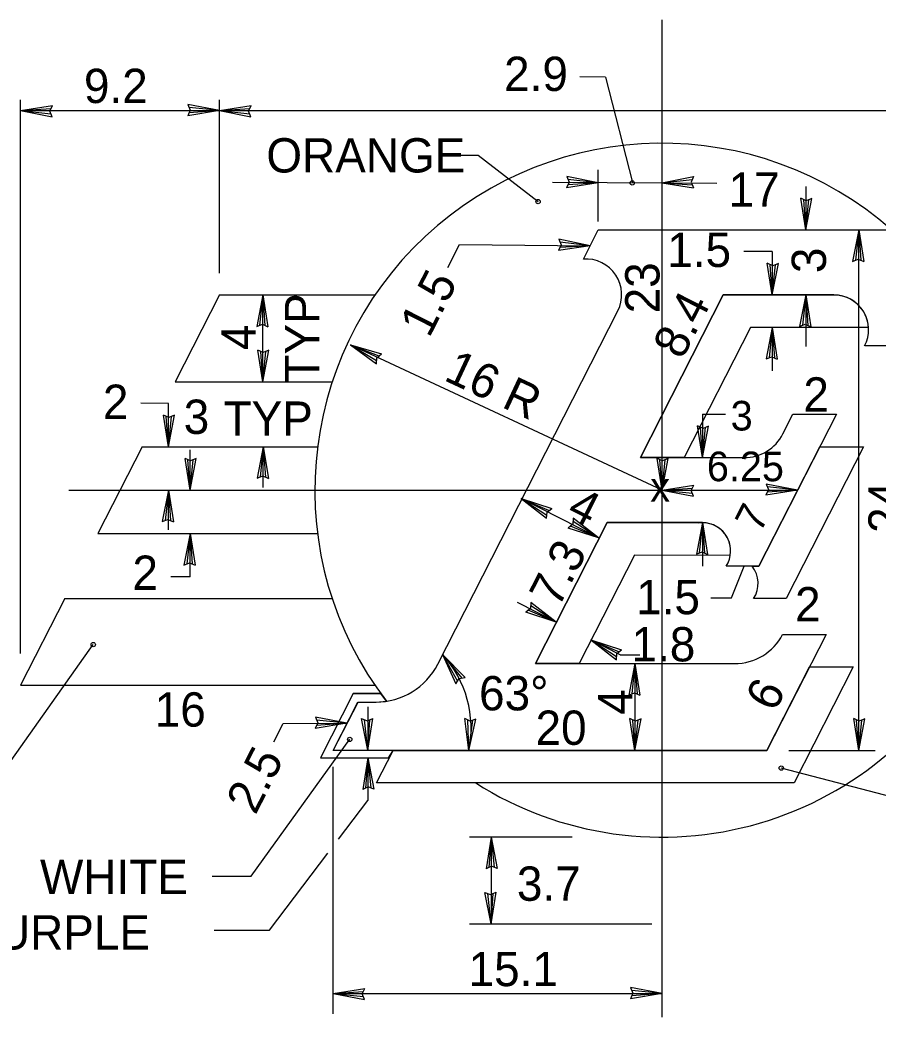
# Model space of a CAD drawing. Extents: x 10268197 to 10269179, y 2141503 to 2142677.
# Drawn here: x 10268467.86 to 10268485.36, y 2142117.75 to 2142138.09 of the extents above; entities that cross this region are included whole.
import ezdxf

# ---------------------------------------------------------------- set-up
doc = ezdxf.new("R2010")
doc.units = 0
for name, color, linetype in [('1', 7, 'Continuous'), ('2', 7, 'Continuous'), ('52', 7, 'Continuous'), ('SOILS_SP83_SHP', 7, 'Continuous')]:
    doc.layers.add(name, color=color, linetype=linetype)

msp = doc.modelspace()

# ---------------------------------------------------------------- linework, layer by layer
at = {"layer": '1'}
for p, q in [((10268480.958, 2142117.747), (10268480.958, 2142138.09)), ((10268479.802, 2142136.926), (10268479.281, 2142136.929)), ((10268479.802, 2142136.926), (10268480.353, 2142134.772)), ((10268467.878, 2142125.164), (10268467.878, 2142136.461)), ((10268471.932, 2142132.921), (10268471.932, 2142136.461)), ((10268467.878, 2142136.24), (10268491.08, 2142136.24)), ((10268476.41, 2142135.328), (10268477.21, 2142135.328)), ((10268477.21, 2142135.328), (10268478.431, 2142134.386)), ((10268479.658, 2142133.976), (10268479.658, 2142135.032)), ((10268482.078, 2142134.75), (10268478.725, 2142134.774)), ((10268483.89, 2142134.691), (10268483.89, 2142133.806)), ((10268484.969, 2142123.188), (10268484.969, 2142133.806)), ((10268476.59, 2142133.039), (10268476.829, 2142133.508)), ((10268476.829, 2142133.508), (10268479.495, 2142133.484)), ((10268483.206, 2142133.364), (10268482.628, 2142133.364)), ((10268483.206, 2142133.364), (10268483.206, 2142132.479)), ((10268472.817, 2142130.709), (10268472.817, 2142132.479)), ((10268480.517, 2142129.161), (10268482.207, 2142132.479)), ((10268482.207, 2142132.479), (10268484.462, 2142132.479)), ((10268483.89, 2142132.479), (10268483.89, 2142131.427)), ((10268482.763, 2142131.815), (10268481.411, 2142129.161)), ((10268485.17, 2142131.815), (10268482.763, 2142131.815)), ((10268483.206, 2142131.815), (10268483.206, 2142130.93)), ((10268480.958, 2142128.497), (10268474.605, 2142131.459)), ((10268470.892, 2142130.267), (10268470.332, 2142130.27)), ((10268470.892, 2142129.382), (10268470.892, 2142130.267)), ((10268481.783, 2142130.046), (10268481.783, 2142129.161)), ((10268481.783, 2142130.046), (10268482.252, 2142130.046)), ((10268471.334, 2142128.497), (10268471.334, 2142129.322)), ((10268472.827, 2142128.552), (10268472.827, 2142129.382)), ((10268482.934, 2142126.949), (10268484.174, 2142129.382)), ((10268485.067, 2142129.382), (10268483.489, 2142126.285)), ((10268484.174, 2142129.382), (10268485.067, 2142129.382)), ((10268481.411, 2142129.161), (10268480.517, 2142129.161)), ((10268468.86, 2142128.497), (10268483.723, 2142128.497)), ((10268470.892, 2142127.689), (10268470.892, 2142128.497)), ((10268479.664, 2142127.521), (10268478.087, 2142128.325)), ((10268478.376, 2142124.957), (10268479.841, 2142127.834)), ((10268479.841, 2142127.834), (10268481.699, 2142127.827)), ((10268481.783, 2142127.834), (10268481.783, 2142126.949)), ((10268471.334, 2142126.727), (10268471.334, 2142127.612)), ((10268480.396, 2142127.168), (10268479.269, 2142124.957)), ((10268482.349, 2142127.162), (10268480.396, 2142127.168)), ((10268482.375, 2142126.297), (10268482.631, 2142126.949)), ((10268482.795, 2142126.949), (10268482.934, 2142126.949)), ((10268471.334, 2142126.727), (10268470.943, 2142126.731)), ((10268481.95, 2142126.297), (10268482.375, 2142126.297)), ((10268483.489, 2142126.285), (10268482.826, 2142126.285)), ((10268478.8, 2142125.802), (10268478.012, 2142126.204)), ((10268480.101, 2142125.139), (10268479.509, 2142125.44)), ((10268467.601, 2142122.868), (10268469.358, 2142125.347)), ((10268480.101, 2142125.139), (10268480.508, 2142125.139)), ((10268479.269, 2142124.957), (10268478.376, 2142124.957)), ((10268480.406, 2142124.957), (10268480.406, 2142123.188)), ((10268483.097, 2142123.188), (10268483.964, 2142124.89)), ((10268484.858, 2142124.89), (10268483.653, 2142122.524)), ((10268483.964, 2142124.89), (10268484.858, 2142124.89)), ((10268474.957, 2142124.074), (10268474.957, 2142123.195)), ((10268473.044, 2142123.365), (10268473.233, 2142123.734)), ((10268473.233, 2142123.734), (10268474.533, 2142123.745)), ((10268472.582, 2142120.624), (10268474.589, 2142123.413)), ((10268475.134, 2142122.524), (10268475.472, 2142123.188)), ((10268475.472, 2142123.188), (10268483.097, 2142123.188)), ((10268483.54, 2142123.188), (10268485.301, 2142123.188)), ((10268474.957, 2142123.038), (10268474.957, 2142122.165)), ((10268474.249, 2142117.811), (10268474.249, 2142122.849)), ((10268485.66, 2142122.233), (10268483.388, 2142122.827)), ((10268483.653, 2142122.524), (10268475.134, 2142122.524)), ((10268474.357, 2142121.373), (10268474.957, 2142122.165)), ((10268479.125, 2142121.418), (10268477.03, 2142121.418)), ((10268477.472, 2142121.418), (10268477.472, 2142119.648)), ((10268472.952, 2142119.519), (10268474.144, 2142121.093)), ((10268471.781, 2142120.624), (10268472.582, 2142120.624)), ((10268471.828, 2142119.519), (10268472.952, 2142119.519)), ((10268477.03, 2142119.648), (10268480.75, 2142119.648)), ((10268474.249, 2142118.227), (10268480.958, 2142118.227))]:
    msp.add_line(p, q, dxfattribs=at)
msp.add_lwpolyline([(10268475.223, 2142124.346), (10268474.658, 2142124.346), (10268473.993, 2142123.038), (10268475.38, 2142123.038), (10268475.472, 2142123.188), (10268474.249, 2142123.188), (10268474.764, 2142124.173), (10268475.127, 2142124.173), (10268475.339, 2142124.19)], close=True, dxfattribs=at)
for centre in [(10268480.35, 2142134.766), (10268478.431, 2142134.385), (10268469.358, 2142125.346), (10268474.589, 2142123.412), (10268483.388, 2142122.826)]:
    msp.add_circle(centre, 0.0442, dxfattribs=at)
for centre, radius, start, end in [((10268484.463, 2142131.77), 0.708, 3.5833, 90), ((10268481.782, 2142127.257), 0.575, 350.3502, 98.3344), ((10268482.341, 2142126.594), 0.575, 327.421, 37.9799), ((10268474.852, 2142123.646), 2.212, 348.03, 42.5026)]:
    msp.add_arc(centre, radius, start, end, dxfattribs=at)
at = {"layer": '2'}
for p, q in [((10268474.658, 2142124.346), (10268473.993, 2142123.038)), ((10268474.658, 2142124.346), (10268475.223, 2142124.346)), ((10268473.993, 2142123.038), (10268475.38, 2142123.038))]:
    msp.add_line(p, q, dxfattribs=at)
at = {"layer": '52'}
for p, q in [((10268467.878, 2142136.24), (10268468.525, 2142136.342)), ((10268467.878, 2142136.24), (10268468.498, 2142136.283)), ((10268467.878, 2142136.24), (10268468.521, 2142136.114)), ((10268467.878, 2142136.24), (10268468.496, 2142136.174)), ((10268468.474, 2142136.229), (10268468.525, 2142136.342)), ((10268468.521, 2142136.114), (10268468.474, 2142136.229)), ((10268471.337, 2142136.249), (10268471.285, 2142136.137)), ((10268471.932, 2142136.24), (10268471.285, 2142136.137)), ((10268471.932, 2142136.24), (10268471.289, 2142136.364)), ((10268471.289, 2142136.364), (10268471.337, 2142136.249)), ((10268471.932, 2142136.24), (10268471.313, 2142136.196)), ((10268471.932, 2142136.24), (10268471.314, 2142136.304)), ((10268471.932, 2142136.24), (10268472.579, 2142136.342)), ((10268471.932, 2142136.24), (10268472.552, 2142136.283)), ((10268471.932, 2142136.24), (10268472.575, 2142136.114)), ((10268471.932, 2142136.24), (10268472.55, 2142136.174)), ((10268472.527, 2142136.229), (10268472.579, 2142136.342)), ((10268472.575, 2142136.114), (10268472.527, 2142136.229)), ((10268479.061, 2142134.781), (10268479.009, 2142134.668)), ((10268479.657, 2142134.765), (10268479.015, 2142134.896)), ((10268479.015, 2142134.896), (10268479.061, 2142134.781)), ((10268479.657, 2142134.765), (10268479.039, 2142134.835)), ((10268480.954, 2142134.765), (10268481.596, 2142134.896)), ((10268480.954, 2142134.765), (10268481.571, 2142134.835)), ((10268481.596, 2142134.896), (10268481.55, 2142134.781)), ((10268481.55, 2142134.781), (10268481.602, 2142134.668)), ((10268479.657, 2142134.765), (10268479.009, 2142134.668)), ((10268479.657, 2142134.765), (10268479.037, 2142134.727)), ((10268480.954, 2142134.765), (10268481.602, 2142134.668)), ((10268480.954, 2142134.765), (10268481.574, 2142134.727)), ((10268483.89, 2142133.806), (10268483.787, 2142134.453)), ((10268483.899, 2142134.402), (10268483.787, 2142134.453)), ((10268483.89, 2142133.806), (10268483.846, 2142134.425)), ((10268483.89, 2142133.806), (10268484.014, 2142134.449)), ((10268483.89, 2142133.806), (10268483.954, 2142134.424)), ((10268484.014, 2142134.449), (10268483.899, 2142134.402)), ((10268484.969, 2142133.806), (10268484.844, 2142133.163)), ((10268484.969, 2142133.806), (10268484.904, 2142133.188)), ((10268484.969, 2142133.806), (10268485.072, 2142133.159)), ((10268484.969, 2142133.806), (10268485.012, 2142133.187)), ((10268479.495, 2142133.484), (10268478.853, 2142133.615)), ((10268478.853, 2142133.615), (10268478.899, 2142133.5)), ((10268478.899, 2142133.5), (10268478.847, 2142133.387)), ((10268479.495, 2142133.484), (10268478.847, 2142133.387)), ((10268479.495, 2142133.484), (10268478.875, 2142133.446)), ((10268479.495, 2142133.484), (10268478.878, 2142133.554)), ((10268484.844, 2142133.163), (10268484.958, 2142133.21)), ((10268484.958, 2142133.21), (10268485.072, 2142133.159)), ((10268483.206, 2142132.479), (10268483.103, 2142133.126)), ((10268483.215, 2142133.074), (10268483.103, 2142133.126)), ((10268483.206, 2142132.479), (10268483.162, 2142133.098)), ((10268483.206, 2142132.479), (10268483.33, 2142133.121)), ((10268483.206, 2142132.479), (10268483.27, 2142133.097)), ((10268483.33, 2142133.121), (10268483.215, 2142133.074)), ((10268472.817, 2142132.479), (10268472.692, 2142131.836)), ((10268472.817, 2142132.479), (10268472.752, 2142131.861)), ((10268472.817, 2142132.479), (10268472.92, 2142131.832)), ((10268472.817, 2142132.479), (10268472.861, 2142131.859)), ((10268483.89, 2142132.479), (10268483.764, 2142131.836)), ((10268483.89, 2142132.479), (10268483.825, 2142131.861)), ((10268483.89, 2142132.479), (10268483.992, 2142131.832)), ((10268483.89, 2142132.479), (10268483.933, 2142131.859)), ((10268472.692, 2142131.836), (10268472.807, 2142131.883)), ((10268472.807, 2142131.883), (10268472.92, 2142131.832)), ((10268483.206, 2142131.815), (10268483.081, 2142131.173)), ((10268483.206, 2142131.815), (10268483.141, 2142131.197)), ((10268483.206, 2142131.815), (10268483.308, 2142131.168)), ((10268483.206, 2142131.815), (10268483.249, 2142131.196)), ((10268483.764, 2142131.836), (10268483.879, 2142131.883)), ((10268483.879, 2142131.883), (10268483.992, 2142131.832)), ((10268472.817, 2142130.709), (10268472.714, 2142131.356)), ((10268472.827, 2142131.305), (10268472.714, 2142131.356)), ((10268472.817, 2142130.709), (10268472.774, 2142131.328)), ((10268472.817, 2142130.709), (10268472.942, 2142131.352)), ((10268472.817, 2142130.709), (10268472.881, 2142131.327)), ((10268472.942, 2142131.352), (10268472.827, 2142131.305)), ((10268474.605, 2142131.459), (10268475.234, 2142131.279)), ((10268474.605, 2142131.459), (10268475.135, 2142131.075)), ((10268474.605, 2142131.459), (10268475.137, 2142131.14)), ((10268474.605, 2142131.459), (10268475.184, 2142131.237)), ((10268475.135, 2142131.075), (10268475.14, 2142131.199)), ((10268475.14, 2142131.199), (10268475.234, 2142131.279)), ((10268483.081, 2142131.173), (10268483.196, 2142131.219)), ((10268483.196, 2142131.219), (10268483.308, 2142131.168)), ((10268470.892, 2142129.382), (10268470.789, 2142130.029)), ((10268470.902, 2142129.977), (10268470.789, 2142130.029)), ((10268470.892, 2142129.382), (10268470.849, 2142130.001)), ((10268470.892, 2142129.382), (10268471.017, 2142130.024)), ((10268470.892, 2142129.382), (10268470.957, 2142130)), ((10268471.017, 2142130.024), (10268470.902, 2142129.977)), ((10268481.783, 2142129.161), (10268481.68, 2142129.808)), ((10268481.793, 2142129.756), (10268481.68, 2142129.808)), ((10268481.783, 2142129.161), (10268481.739, 2142129.78)), ((10268481.783, 2142129.161), (10268481.907, 2142129.803)), ((10268481.783, 2142129.161), (10268481.847, 2142129.779)), ((10268481.907, 2142129.803), (10268481.793, 2142129.756)), ((10268472.827, 2142129.382), (10268472.703, 2142128.739)), ((10268472.827, 2142129.382), (10268472.763, 2142128.764)), ((10268472.827, 2142129.382), (10268472.93, 2142128.735)), ((10268472.827, 2142129.382), (10268472.871, 2142128.762)), ((10268471.334, 2142128.497), (10268471.232, 2142129.144)), ((10268471.344, 2142129.092), (10268471.232, 2142129.144)), ((10268471.334, 2142128.497), (10268471.291, 2142129.116)), ((10268471.334, 2142128.497), (10268471.459, 2142129.14)), ((10268471.334, 2142128.497), (10268471.399, 2142129.115)), ((10268471.459, 2142129.14), (10268471.344, 2142129.092)), ((10268480.958, 2142128.497), (10268480.855, 2142129.144)), ((10268480.968, 2142129.092), (10268480.855, 2142129.144)), ((10268480.958, 2142128.497), (10268480.914, 2142129.116)), ((10268480.958, 2142128.497), (10268481.082, 2142129.14)), ((10268480.958, 2142128.497), (10268481.022, 2142129.115)), ((10268481.082, 2142129.14), (10268480.968, 2142129.092)), ((10268472.703, 2142128.739), (10268472.817, 2142128.786)), ((10268472.817, 2142128.786), (10268472.93, 2142128.735)), ((10268470.892, 2142128.497), (10268470.767, 2142127.854)), ((10268470.892, 2142128.497), (10268470.827, 2142127.879)), ((10268470.892, 2142128.497), (10268470.995, 2142127.85)), ((10268470.892, 2142128.497), (10268470.935, 2142127.877)), ((10268480.958, 2142128.497), (10268481.605, 2142128.599)), ((10268480.958, 2142128.497), (10268481.577, 2142128.54)), ((10268480.958, 2142128.497), (10268481.6, 2142128.372)), ((10268480.958, 2142128.497), (10268481.576, 2142128.432)), ((10268481.553, 2142128.487), (10268481.605, 2142128.599)), ((10268481.6, 2142128.372), (10268481.553, 2142128.487)), ((10268483.127, 2142128.507), (10268483.076, 2142128.394)), ((10268483.723, 2142128.497), (10268483.076, 2142128.394)), ((10268483.723, 2142128.497), (10268483.08, 2142128.622)), ((10268483.08, 2142128.622), (10268483.127, 2142128.507)), ((10268483.723, 2142128.497), (10268483.103, 2142128.453)), ((10268483.723, 2142128.497), (10268483.105, 2142128.562)), ((10268478.087, 2142128.325), (10268478.71, 2142128.123)), ((10268478.087, 2142128.325), (10268478.603, 2142127.922)), ((10268478.087, 2142128.325), (10268478.608, 2142127.987)), ((10268478.087, 2142128.325), (10268478.659, 2142128.082)), ((10268478.613, 2142128.046), (10268478.71, 2142128.123)), ((10268470.767, 2142127.854), (10268470.882, 2142127.901)), ((10268470.882, 2142127.901), (10268470.995, 2142127.85)), ((10268478.603, 2142127.922), (10268478.613, 2142128.046)), ((10268479.148, 2142127.925), (10268479.138, 2142127.801)), ((10268479.664, 2142127.521), (10268479.143, 2142127.86)), ((10268479.664, 2142127.521), (10268479.148, 2142127.925)), ((10268479.138, 2142127.801), (10268479.041, 2142127.723)), ((10268479.664, 2142127.521), (10268479.041, 2142127.723)), ((10268479.664, 2142127.521), (10268479.092, 2142127.764)), ((10268481.783, 2142127.834), (10268481.658, 2142127.191)), ((10268481.783, 2142127.834), (10268481.718, 2142127.215)), ((10268481.783, 2142127.834), (10268481.886, 2142127.186)), ((10268481.783, 2142127.834), (10268481.826, 2142127.214)), ((10268471.334, 2142127.612), (10268471.209, 2142126.969)), ((10268471.334, 2142127.612), (10268471.269, 2142126.994)), ((10268471.334, 2142127.612), (10268471.437, 2142126.965)), ((10268471.334, 2142127.612), (10268471.378, 2142126.993)), ((10268481.658, 2142127.191), (10268481.773, 2142127.237)), ((10268481.773, 2142127.237), (10268481.886, 2142127.186)), ((10268471.209, 2142126.969), (10268471.324, 2142127.016)), ((10268471.324, 2142127.016), (10268471.437, 2142126.965)), ((10268478.274, 2142126.082), (10268478.177, 2142126.005)), ((10268478.8, 2142125.802), (10268478.229, 2142126.045)), ((10268478.284, 2142126.206), (10268478.274, 2142126.082)), ((10268478.8, 2142125.802), (10268478.279, 2142126.14)), ((10268478.8, 2142125.802), (10268478.284, 2142126.206)), ((10268478.8, 2142125.802), (10268478.177, 2142126.005)), ((10268479.509, 2142125.44), (10268480.132, 2142125.238)), ((10268479.509, 2142125.44), (10268480.026, 2142125.037)), ((10268479.509, 2142125.44), (10268480.031, 2142125.102)), ((10268479.509, 2142125.44), (10268480.081, 2142125.198)), ((10268480.036, 2142125.161), (10268480.132, 2142125.238)), ((10268476.483, 2142125.141), (10268476.942, 2142124.674)), ((10268476.483, 2142125.141), (10268476.755, 2142124.545)), ((10268476.483, 2142125.141), (10268476.789, 2142124.601)), ((10268476.483, 2142125.141), (10268476.878, 2142124.662)), ((10268480.026, 2142125.037), (10268480.036, 2142125.161)), ((10268480.406, 2142124.957), (10268480.28, 2142124.315)), ((10268480.406, 2142124.957), (10268480.341, 2142124.34)), ((10268480.406, 2142124.957), (10268480.508, 2142124.311)), ((10268480.406, 2142124.957), (10268480.449, 2142124.338)), ((10268476.755, 2142124.545), (10268476.82, 2142124.651)), ((10268476.82, 2142124.651), (10268476.942, 2142124.674)), ((10268480.28, 2142124.315), (10268480.395, 2142124.362)), ((10268480.395, 2142124.362), (10268480.508, 2142124.311)), ((10268474.533, 2142123.745), (10268473.889, 2142123.864)), ((10268473.889, 2142123.864), (10268473.937, 2142123.75)), ((10268474.533, 2142123.745), (10268473.914, 2142123.805)), ((10268474.957, 2142123.195), (10268474.832, 2142123.837)), ((10268474.832, 2142123.837), (10268474.946, 2142123.79)), ((10268474.957, 2142123.195), (10268474.892, 2142123.812)), ((10268474.946, 2142123.79), (10268475.059, 2142123.841)), ((10268474.957, 2142123.195), (10268475.059, 2142123.841)), ((10268474.957, 2142123.195), (10268475, 2142123.814)), ((10268477.016, 2142123.188), (10268476.936, 2142123.838)), ((10268477.047, 2142123.782), (10268476.936, 2142123.838)), ((10268477.016, 2142123.188), (10268476.995, 2142123.809)), ((10268477.016, 2142123.188), (10268477.163, 2142123.826)), ((10268477.016, 2142123.188), (10268477.102, 2142123.803)), ((10268477.163, 2142123.826), (10268477.047, 2142123.782)), ((10268480.406, 2142123.188), (10268480.303, 2142123.835)), ((10268480.415, 2142123.783), (10268480.303, 2142123.835)), ((10268480.406, 2142123.188), (10268480.362, 2142123.807)), ((10268480.406, 2142123.188), (10268480.53, 2142123.83)), ((10268480.406, 2142123.188), (10268480.47, 2142123.806)), ((10268480.53, 2142123.83), (10268480.415, 2142123.783)), ((10268484.969, 2142123.188), (10268484.866, 2142123.835)), ((10268484.979, 2142123.783), (10268484.866, 2142123.835)), ((10268484.969, 2142123.188), (10268484.925, 2142123.807)), ((10268484.969, 2142123.188), (10268485.093, 2142123.83)), ((10268484.969, 2142123.188), (10268485.033, 2142123.806)), ((10268485.093, 2142123.83), (10268484.979, 2142123.783)), ((10268473.937, 2142123.75), (10268473.887, 2142123.637)), ((10268474.533, 2142123.745), (10268473.887, 2142123.637)), ((10268474.533, 2142123.745), (10268473.914, 2142123.696)), ((10268474.957, 2142123.038), (10268474.854, 2142122.391)), ((10268474.957, 2142123.038), (10268474.913, 2142122.418)), ((10268474.957, 2142123.038), (10268475.081, 2142122.394)), ((10268474.957, 2142123.038), (10268475.021, 2142122.419)), ((10268474.967, 2142122.442), (10268474.854, 2142122.391)), ((10268475.081, 2142122.394), (10268474.967, 2142122.442)), ((10268477.472, 2142121.418), (10268477.369, 2142120.771)), ((10268477.472, 2142121.418), (10268477.428, 2142120.799)), ((10268477.472, 2142121.418), (10268477.596, 2142120.775)), ((10268477.472, 2142121.418), (10268477.536, 2142120.8)), ((10268477.481, 2142120.822), (10268477.369, 2142120.771)), ((10268477.596, 2142120.775), (10268477.481, 2142120.822)), ((10268477.472, 2142119.648), (10268477.347, 2142120.291)), ((10268477.347, 2142120.291), (10268477.462, 2142120.244)), ((10268477.472, 2142119.648), (10268477.407, 2142120.266)), ((10268477.462, 2142120.244), (10268477.575, 2142120.295)), ((10268477.472, 2142119.648), (10268477.575, 2142120.295)), ((10268477.472, 2142119.648), (10268477.515, 2142120.268)), ((10268474.249, 2142118.227), (10268474.896, 2142118.33)), ((10268474.844, 2142118.218), (10268474.896, 2142118.33)), ((10268480.958, 2142118.227), (10268480.313, 2142118.347)), ((10268480.313, 2142118.347), (10268480.362, 2142118.233)), ((10268474.249, 2142118.227), (10268474.868, 2142118.271)), ((10268474.249, 2142118.227), (10268474.892, 2142118.103)), ((10268474.249, 2142118.227), (10268474.867, 2142118.163)), ((10268474.892, 2142118.103), (10268474.844, 2142118.218)), ((10268480.362, 2142118.233), (10268480.312, 2142118.119)), ((10268480.958, 2142118.227), (10268480.312, 2142118.119)), ((10268480.958, 2142118.227), (10268480.339, 2142118.287)), ((10268480.958, 2142118.227), (10268480.339, 2142118.179))]:
    msp.add_line(p, q, dxfattribs=at)
at = {"layer": 'SOILS_SP83_SHP'}
for p, q in [((10268479.357, 2142133.212), (10268479.658, 2142133.806)), ((10268479.658, 2142133.806), (10268487.18, 2142133.806)), ((10268471.932, 2142132.479), (10268471.031, 2142130.709)), ((10268471.932, 2142132.479), (10268475.105, 2142132.479)), ((10268482.207, 2142132.479), (10268480.517, 2142129.161)), ((10268480.517, 2142129.161), (10268482.207, 2142132.479)), ((10268484.462, 2142132.479), (10268482.207, 2142132.479)), ((10268482.207, 2142132.479), (10268484.462, 2142132.479)), ((10268476.384, 2142124.946), (10268480.056, 2142132.153)), ((10268482.763, 2142131.815), (10268481.411, 2142129.161)), ((10268485.17, 2142131.815), (10268482.763, 2142131.815)), ((10268485.975, 2142131.441), (10268485.09, 2142131.441)), ((10268471.031, 2142130.709), (10268474.233, 2142130.709)), ((10268484.512, 2142130.046), (10268482.934, 2142126.949)), ((10268483.422, 2142129.644), (10268483.627, 2142130.046)), ((10268483.627, 2142130.046), (10268484.512, 2142130.046)), ((10268470.356, 2142129.382), (10268469.455, 2142127.612)), ((10268470.356, 2142129.382), (10268473.934, 2142129.382)), ((10268482.934, 2142126.949), (10268484.174, 2142129.382)), ((10268485.067, 2142129.382), (10268483.489, 2142126.285)), ((10268484.174, 2142129.382), (10268485.067, 2142129.382)), ((10268480.517, 2142129.161), (10268482.634, 2142129.161)), ((10268481.411, 2142129.161), (10268480.517, 2142129.161)), ((10268479.841, 2142127.834), (10268478.376, 2142124.957)), ((10268478.376, 2142124.957), (10268479.841, 2142127.834)), ((10268481.783, 2142127.834), (10268479.841, 2142127.834)), ((10268479.841, 2142127.834), (10268481.699, 2142127.827)), ((10268469.455, 2142127.612), (10268473.934, 2142127.612)), ((10268480.396, 2142127.168), (10268479.269, 2142124.957)), ((10268482.349, 2142127.162), (10268480.396, 2142127.168)), ((10268482.934, 2142126.949), (10268482.267, 2142126.949)), ((10268482.795, 2142126.949), (10268482.934, 2142126.949)), ((10268468.779, 2142126.285), (10268467.878, 2142124.515)), ((10268468.779, 2142126.285), (10268474.233, 2142126.285)), ((10268483.489, 2142126.285), (10268482.826, 2142126.285)), ((10268484.303, 2142125.553), (10268483.097, 2142123.188)), ((10268483.417, 2142125.553), (10268484.303, 2142125.553)), ((10268478.376, 2142124.957), (10268482.436, 2142124.957)), ((10268479.269, 2142124.957), (10268478.376, 2142124.957)), ((10268483.097, 2142123.188), (10268483.964, 2142124.89)), ((10268484.858, 2142124.89), (10268483.653, 2142122.524)), ((10268483.964, 2142124.89), (10268484.858, 2142124.89)), ((10268467.878, 2142124.515), (10268475.105, 2142124.515)), ((10268474.249, 2142123.188), (10268474.751, 2142124.173)), ((10268474.751, 2142124.173), (10268475.122, 2142124.173)), ((10268483.097, 2142123.188), (10268474.249, 2142123.188)), ((10268475.134, 2142122.524), (10268475.472, 2142123.188)), ((10268475.472, 2142123.188), (10268483.097, 2142123.188)), ((10268483.653, 2142122.524), (10268475.134, 2142122.524))]:
    msp.add_line(p, q, dxfattribs=at)
for centre, radius, start, end in [((10268480.957, 2142128.496), 7.079, 48.5904, 217.4727), ((10268479.405, 2142132.484), 0.73, 332.9998, 93.8045), ((10268484.463, 2142131.77), 0.708, 332.2089, 90), ((10268484.463, 2142131.77), 0.708, 3.5833, 90), ((10268482.634, 2142130.045), 0.885, 270, 332.9883), ((10268481.782, 2142127.257), 0.575, 350.3502, 98.3344), ((10268481.782, 2142127.257), 0.575, 327.421, 90), ((10268482.341, 2142126.594), 0.575, 327.421, 37.9799), ((10268480.957, 2142128.496), 7.079, 237.5383, 335.047), ((10268482.436, 2142126.063), 1.106, 270, 332.5096), ((10268475.122, 2142125.589), 1.416, 270, 332.9991)]:
    msp.add_arc(centre, radius, start, end, dxfattribs=at)

# ---------------------------------------------------------------- texts
at = {"layer": '1'}
for s, height, p in [('2.9', 0.7, (10268477.737, 2142136.641)), ('9.2', 0.7, (10268469.169, 2142136.395)), ('ORANGE', 0.7, (10268472.889, 2142134.978)), ('17', 0.7, (10268482.314, 2142134.279)), ('1.5', 0.7, (10268481.064, 2142133.05)), ('2', 0.7, (10268483.84, 2142130.099)), ('2', 0.7, (10268469.556, 2142129.95)), ('3', 0.7, (10268471.204, 2142129.644)), ('TYP', 0.7, (10268472.016, 2142129.606)), ('3', 0.604, (10268482.357, 2142129.714)), ('6.25', 0.6037, (10268481.872, 2142128.679)), ('x', 0.604, (10268480.717, 2142128.261)), ('2', 0.7, (10268470.158, 2142126.462)), ('1.5', 0.7, (10268480.429, 2142125.966)), ('2', 0.7, (10268483.67, 2142125.82)), ('1.8', 0.7, (10268480.335, 2142125.003)), ('63°', 0.7, (10268477.226, 2142124.004)), ('16', 0.7, (10268470.613, 2142123.672)), ('20', 0.7, (10268478.378, 2142123.3)), ('WHITE', 0.7, (10268468.273, 2142120.256)), ('3.7', 0.7, (10268477.998, 2142120.119)), ('0.13" PURPLE', 0.7, (10268464.357, 2142119.125)), ('15.1', 0.7, (10268477.012, 2142118.377))]:
    msp.add_text(s, height=height, dxfattribs=at).set_placement(p)
for s, height, rotation, p in [('3', 0.7, 90, (10268484.301, 2142132.925)), ('1.5', 0.7, 63, (10268476.208, 2142131.585)), ('23', 0.7, 90, (10268480.906, 2142132.104)), ('TYP', 0.7, 90, (10268473.969, 2142130.693)), ('8.4', 0.7, 63, (10268481.367, 2142131.141)), ('4', 0.7, 90, (10268472.672, 2142131.354)), ('16 R', 0.7, 334.9991, (10268476.485, 2142130.75)), ('24', 0.7, 90, (10268485.866, 2142127.625)), ('4', 0.7, 332.9866, (10268478.984, 2142127.964)), ('7', 0.604, 63, (10268482.958, 2142127.606)), ('7.3', 0.7, 63, (10268478.847, 2142126.078)), ('6', 0.7, 63, (10268483.255, 2142123.947)), ('4', 0.7, 90, (10268480.351, 2142123.915)), ('2.5', 0.7, 63, (10268472.666, 2142121.854))]:
    msp.add_text(s, height=height, rotation=rotation, dxfattribs=at).set_placement(p)

doc.saveas('drawing.dxf')
